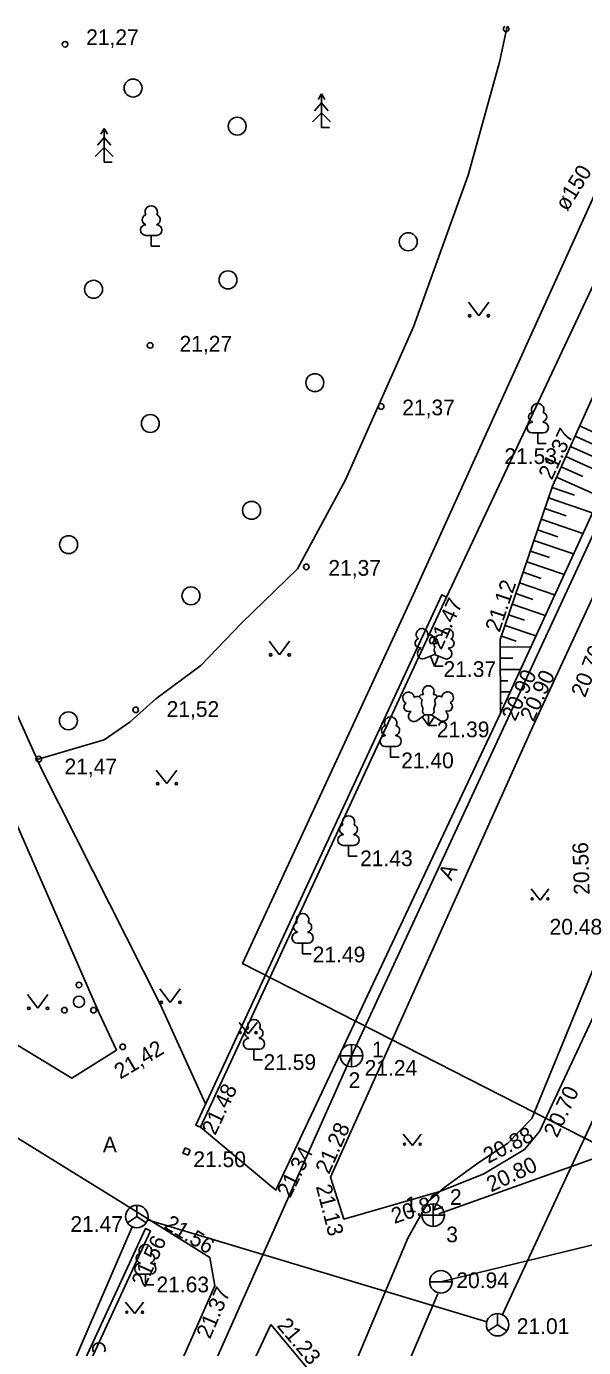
# Model space of a CAD drawing. Extents: x 714391 to 714584, y 6589993 to 6590151.
# Drawn here: x 714424.1 to 714448.9, y 6590092.2 to 6590151.1 of the extents above; entities that cross this region are included whole.
import ezdxf

# ---------------------------------------------------------------- set-up
doc = ezdxf.new("R2010")
doc.units = 0
for name, color, linetype in [('AED', 7, 'Continuous'), ('HALJASTUS', 7, 'Continuous'), ('HOONE', 7, 'Continuous'), ('KKAEV', 7, 'Continuous'), ('KORGUS', 7, 'Continuous'), ('KTRASS', 7, 'Continuous'), ('MPKAABEL', 7, 'Continuous'), ('PUU', 7, 'Continuous'), ('RELJEEF', 7, 'Continuous'), ('SIKAEV', 7, 'Continuous'), ('SITRASS', 7, 'Continuous'), ('SKKAEV', 7, 'Continuous'), ('SKTRASS', 7, 'Continuous'), ('TEE', 7, 'Continuous'), ('TORU NR', 7, 'Continuous'), ('VKAEV', 7, 'Continuous'), ('VTRASS', 7, 'Continuous')]:
    doc.layers.add(name, color=color, linetype=linetype)

msp = doc.modelspace()

# ---------------------------------------------------------------- linework, layer by layer
at = {"layer": 'AED'}
for p, q in [((714431.182, 6590101.096), (714431.081, 6590100.867)), ((714431.182, 6590101.096), (714431.411, 6590100.995)), ((714431.411, 6590100.995), (714431.31, 6590100.766)), ((714431.081, 6590100.867), (714431.31, 6590100.766))]:
    msp.add_line(p, q, dxfattribs=at)
for points in [[(714442.826, 6590125.646), (714454.774, 6590151.075)], [(714419.286, 6590087.641), (714423.948, 6590085.67), (714429.409, 6590097.501), (714429.636, 6590097.396), (714424.08, 6590085.358), (714419.194, 6590087.423)]]:
    msp.add_lwpolyline(points, dxfattribs=at)
msp.add_lwpolyline([(714431.863, 6590102.016), (714442.826, 6590125.646), (714442.618, 6590125.749), (714431.653, 6590102.114)], close=True, dxfattribs=at)
at = {"layer": 'HALJASTUS'}
for p, q in [((714443.797, 6590138.787), (714444.26, 6590138.18)), ((714444.26, 6590138.18), (714444.706, 6590138.787)), ((714434.927, 6590123.677), (714435.39, 6590123.07)), ((714435.39, 6590123.07), (714435.836, 6590123.677)), ((714429.897, 6590117.937), (714430.36, 6590117.33)), ((714430.36, 6590117.33), (714430.806, 6590117.937)), ((714446.589, 6590112.643), (714446.994, 6590112.138)), ((714446.994, 6590112.138), (714447.389, 6590112.643)), ((714430.057, 6590108.187), (714430.52, 6590107.58)), ((714430.52, 6590107.58), (714430.966, 6590108.187)), ((714424.157, 6590107.927), (714424.62, 6590107.32)), ((714424.62, 6590107.32), (714425.066, 6590107.927)), ((714433.585, 6590106.683), (714433.99, 6590106.178)), ((714433.99, 6590106.178), (714434.385, 6590106.683)), ((714440.9, 6590101.716), (714441.305, 6590101.211)), ((714441.305, 6590101.211), (714441.7, 6590101.716)), ((714428.528, 6590094.221), (714428.933, 6590093.716)), ((714428.933, 6590093.716), (714429.328, 6590094.221))]:
    msp.add_line(p, q, dxfattribs=at)
msp.add_lwpolyline([(714445.524, 6590151.075), (714445.18, 6590149.48), (714443.79, 6590144.45), (714441.36, 6590137.69), (714438.33, 6590130.87), (714436.18, 6590126.9), (714433.71, 6590124.5), (714431.88, 6590122.59), (714429.88, 6590121.11), (714428.73, 6590120.08), (714427.57, 6590119.28), (714424.59, 6590118.4)], dxfattribs=at)
for centre, radius in [((714428.86, 6590148.33), 0.4), ((714433.5, 6590146.63), 0.4), ((714441.12, 6590141.48), 0.4), ((714433.09, 6590139.78), 0.4), ((714427.1, 6590139.36), 0.4), ((714443.859, 6590138.18), 0.055), ((714444.688, 6590138.18), 0.055), ((714436.96, 6590135.2), 0.4), ((714429.63, 6590133.38), 0.4), ((714434.14, 6590129.51), 0.4), ((714425.99, 6590127.98), 0.4), ((714431.44, 6590125.7), 0.4), ((714434.989, 6590123.07), 0.055), ((714435.818, 6590123.07), 0.055), ((714425.98, 6590120.13), 0.4), ((714429.959, 6590117.33), 0.055), ((714430.788, 6590117.33), 0.055), ((714446.641, 6590112.194), 0.0428), ((714447.341, 6590112.194), 0.0452), ((714426.45, 6590108.36), 0.125), ((714426.45, 6590107.61), 0.25), ((714430.119, 6590107.58), 0.055), ((714430.948, 6590107.58), 0.055), ((714424.219, 6590107.32), 0.055), ((714425.048, 6590107.32), 0.055), ((714425.8, 6590107.235), 0.125), ((714427.1, 6590107.235), 0.125), ((714433.637, 6590106.233), 0.0428), ((714434.337, 6590106.233), 0.0452), ((714440.952, 6590101.266), 0.0428), ((714441.652, 6590101.266), 0.0452), ((714428.58, 6590093.771), 0.0428), ((714429.28, 6590093.771), 0.0452)]:
    msp.add_circle(centre, radius, dxfattribs=at)
at = {"layer": 'HOONE'}
msp.add_lwpolyline([(714462.081, 6590095.105), (714459.73, 6590096.05), (714433.74, 6590109.31), (714441.36, 6590125.77), (714449.34, 6590143.41), (714452.652, 6590151.075)], dxfattribs=at)
at = {"layer": 'KKAEV'}
for p, q in [((714438.594, 6590104.707), (714438.594, 6590105.707)), ((714438.094, 6590105.207), (714439.094, 6590105.207))]:
    msp.add_line(p, q, dxfattribs=at)
msp.add_circle((714438.594, 6590105.207), 0.5, dxfattribs=at)
at = {"layer": 'KORGUS'}
for centre in [(714425.83, 6590150.28), (714429.62, 6590136.86), (714439.91, 6590134.14), (714436.58, 6590126.99), (714428.98, 6590120.62), (714424.66, 6590118.42), (714428.4, 6590105.6)]:
    msp.add_circle(centre, 0.125, dxfattribs=at)
msp.add_arc((714445.48, 6590150.96), 0.125, 112.49, 67.51, dxfattribs=at)
at = {"layer": 'KTRASS'}
for p in [(714456.211, 6590143.264), (714431.463, 6590089.186)]:
    msp.add_line(p, (714438.594, 6590105.207), dxfattribs=at)
at = {"layer": 'MPKAABEL'}
msp.add_lwpolyline([(714394.611, 6589992.711), (714400.19, 6590004.938), (714412.114, 6590031.265), (714423.696, 6590056.183), (714434.84, 6590082.35), (714435.599, 6590083.495), (714435.59, 6590083.97), (714441.1, 6590097.08), (714442.02, 6590098.72), (714442.75, 6590099.35), (714444.22, 6590100.41), (714445.54, 6590101.3), (714446.63, 6590102.41), (714450.168, 6590111.053), (714453.153, 6590116.846), (714463.66, 6590139.57), (714466.53, 6590147), (714468.444, 6590151.075)], dxfattribs=at)
at = {"layer": 'PUU'}
for p, q in [((714437.25, 6590148.07), (714437.1, 6590147.82)), ((714437.4, 6590147.82), (714437.25, 6590148.07)), ((714437.25, 6590148.07), (714437.25, 6590146.57)), ((714437.25, 6590147.67), (714436.95, 6590147.32)), ((714437.55, 6590147.32), (714437.25, 6590147.67)), ((714437.25, 6590147.22), (714436.85, 6590146.82)), ((714437.65, 6590146.82), (714437.25, 6590147.22)), ((714427.57, 6590146.53), (714427.42, 6590146.28)), ((714427.72, 6590146.28), (714427.57, 6590146.53)), ((714427.57, 6590146.53), (714427.57, 6590145.03)), ((714437.61, 6590146.57), (714437.25, 6590146.57)), ((714427.57, 6590146.13), (714427.27, 6590145.78)), ((714427.87, 6590145.78), (714427.57, 6590146.13)), ((714427.57, 6590145.68), (714427.17, 6590145.28)), ((714427.97, 6590145.28), (714427.57, 6590145.68)), ((714427.93, 6590145.03), (714427.57, 6590145.03)), ((714429.91, 6590141.765), (714429.43, 6590141.765)), ((714429.67, 6590141.29), (714429.67, 6590141.765)), ((714430.05, 6590141.29), (714429.67, 6590141.29)), ((714446.646, 6590133.462), (714446.646, 6590133.432)), ((714447.126, 6590133.462), (714447.126, 6590133.432)), ((714447.126, 6590132.957), (714446.646, 6590132.957)), ((714446.886, 6590132.482), (714446.886, 6590132.957)), ((714447.266, 6590132.482), (714446.886, 6590132.482)), ((714441.674, 6590123.351), (714441.659, 6590123.391)), ((714442.204, 6590123.561), (714442.189, 6590123.596)), ((714442.389, 6590123.556), (714442.404, 6590123.596)), ((714442.914, 6590123.341), (714442.929, 6590123.381)), ((714441.849, 6590122.906), (714442.294, 6590123.081)), ((714442.289, 6590122.571), (714442.114, 6590123.011)), ((714442.289, 6590122.571), (714442.469, 6590123.011)), ((714442.294, 6590123.081), (714442.734, 6590122.901)), ((714442.669, 6590122.571), (714442.289, 6590122.571)), ((714441.23, 6590120.52), (714441.205, 6590120.555)), ((714442.79, 6590120.535), (714442.81, 6590120.57)), ((714441.505, 6590120.135), (714441.865, 6590120.39)), ((714442.015, 6590119.915), (714441.74, 6590120.3)), ((714441.865, 6590120.39), (714442.16, 6590120.39)), ((714442.015, 6590119.915), (714442.015, 6590120.39)), ((714442.015, 6590119.915), (714442.285, 6590120.305)), ((714442.395, 6590119.915), (714442.015, 6590119.915)), ((714442.16, 6590120.39), (714442.52, 6590120.145)), ((714440.094, 6590119.492), (714440.094, 6590119.462)), ((714440.574, 6590119.492), (714440.574, 6590119.462)), ((714440.574, 6590118.987), (714440.094, 6590118.987)), ((714440.334, 6590118.512), (714440.334, 6590118.987)), ((714440.714, 6590118.512), (714440.334, 6590118.512)), ((714438.218, 6590115.082), (714438.218, 6590115.052)), ((714438.698, 6590114.577), (714438.218, 6590114.577)), ((714438.458, 6590114.102), (714438.458, 6590114.577)), ((714438.698, 6590115.082), (714438.698, 6590115.052)), ((714438.838, 6590114.102), (714438.458, 6590114.102)), ((714436.175, 6590110.727), (714436.175, 6590110.697)), ((714436.655, 6590110.727), (714436.655, 6590110.697)), ((714436.655, 6590110.222), (714436.175, 6590110.222)), ((714436.415, 6590109.747), (714436.415, 6590110.222)), ((714436.795, 6590109.747), (714436.415, 6590109.747)), ((714434.007, 6590106.002), (714434.007, 6590105.972)), ((714434.487, 6590106.002), (714434.487, 6590105.972)), ((714434.487, 6590105.497), (714434.007, 6590105.497)), ((714434.247, 6590105.022), (714434.247, 6590105.497)), ((714434.627, 6590105.022), (714434.247, 6590105.022)), ((714429.168, 6590095.976), (714429.168, 6590095.946)), ((714429.648, 6590095.976), (714429.648, 6590095.946)), ((714429.648, 6590095.471), (714429.168, 6590095.471)), ((714429.408, 6590094.996), (714429.408, 6590095.471)), ((714429.788, 6590094.996), (714429.408, 6590094.996))]:
    msp.add_line(p, q, dxfattribs=at)
for points in [[(714442.294, 6590123.576), (714442.274, 6590123.501), (714442.274, 6590123.481), (714442.284, 6590123.451), (714442.304, 6590123.416), (714442.309, 6590123.396), (714442.294, 6590123.361), (714442.269, 6590123.311), (714442.264, 6590123.286), (714442.269, 6590123.271), (714442.279, 6590123.241), (714442.314, 6590123.181), (714442.319, 6590123.161), (714442.314, 6590123.141), (714442.299, 6590123.106), (714442.294, 6590123.081)], [(714441.6, 6590121.2), (714441.705, 6590121.1), (714441.72, 6590121.07), (714441.72, 6590121.015), (714441.705, 6590120.925), (714441.705, 6590120.88), (714441.725, 6590120.8), (714441.765, 6590120.71), (714441.775, 6590120.665), (714441.77, 6590120.62), (714441.755, 6590120.555), (714441.755, 6590120.525), (714441.775, 6590120.485), (714441.8, 6590120.455), (714441.865, 6590120.39)], [(714442.42, 6590121.215), (714442.325, 6590121.1), (714442.31, 6590121.07), (714442.31, 6590121.015), (714442.325, 6590120.925), (714442.33, 6590120.88), (714442.31, 6590120.8), (714442.27, 6590120.71), (714442.26, 6590120.665), (714442.265, 6590120.62), (714442.28, 6590120.555), (714442.28, 6590120.525), (714442.26, 6590120.485), (714442.235, 6590120.455), (714442.165, 6590120.39)]]:
    msp.add_lwpolyline(points, dxfattribs=at)
for centre, radius, start, end in [((714429.67, 6590142.81), 0.277, 332.5799, 207.4201), ((714429.433, 6590142.002), 0.238, 90.0016, 269.3953), ((714429.5, 6590142.463), 0.233, 109.02174, 253.14154), ((714429.84, 6590142.463), 0.233, 286.85082, 70.98591), ((714429.907, 6590142.002), 0.238, 270.6047, 89.9984), ((714446.886, 6590134.002), 0.277, 332.5799, 207.4201), ((714446.649, 6590133.195), 0.237, 90.00001, 270), ((714446.696, 6590133.67), 0.212, 105.2441, 257.07903), ((714447.076, 6590133.67), 0.212, 282.92097, 74.7559), ((714447.124, 6590133.195), 0.237, 270, 89.99999), ((714441.732, 6590123.985), 0.256, 111.50269, 232.51731), ((714441.732, 6590123.985), 0.256, 350.48556, 111.50017), ((714442.075, 6590123.763), 0.202, 305.13446, 116.70496), ((714442.522, 6590123.759), 0.202, 62.41201, 233.98252), ((714442.868, 6590123.976), 0.256, 67.6168, 188.63142), ((714442.868, 6590123.976), 0.256, 306.59966, 67.61428), ((714441.633, 6590123.589), 0.202, 106.29791, 277.86841), ((714441.763, 6590123.129), 0.237, 111.50143, 291.50036), ((714442.293, 6590123.338), 0.237, 66.76552, 111.50149), ((714442.824, 6590123.121), 0.237, 247.61661, 67.61554), ((714442.961, 6590123.579), 0.202, 261.24856, 72.81907), ((714442.015, 6590121.435), 0.256, 90.00126, 211.01588), ((714442.015, 6590121.435), 0.256, 328.98412, 89.99874), ((714441.132, 6590121.152), 0.256, 125.53894, 246.55356), ((714441.132, 6590121.152), 0.256, 4.5218, 125.53642), ((714441.518, 6590121.019), 0.202, 65.23821, 130.74121), ((714441.777, 6590121.103), 0.202, 84.79647, 150.29947), ((714442.252, 6590121.103), 0.202, 34.38566, 95.20353), ((714442.491, 6590121.028), 0.202, 50.31726, 111.13512), ((714442.875, 6590121.168), 0.256, 55.52204, 176.53666), ((714442.875, 6590121.168), 0.256, 294.50491, 55.51952), ((714441.132, 6590120.743), 0.202, 120.33415, 291.90466), ((714441.369, 6590120.329), 0.237, 125.53768, 305.53661), ((714442.653, 6590120.341), 0.237, 235.52186, 55.52078), ((714442.883, 6590120.759), 0.202, 249.15381, 60.72431), ((714440.144, 6590119.7), 0.212, 105.2441, 257.07903), ((714440.334, 6590120.032), 0.277, 332.5799, 207.4201), ((714440.524, 6590119.7), 0.212, 282.92097, 74.7559), ((714440.096, 6590119.225), 0.237, 90.00001, 270), ((714440.571, 6590119.225), 0.237, 270, 89.99999), ((714438.458, 6590115.622), 0.277, 332.5799, 207.4201), ((714438.268, 6590115.29), 0.212, 105.2441, 257.07903), ((714438.648, 6590115.29), 0.212, 282.92097, 74.7559), ((714438.22, 6590114.815), 0.237, 90.00001, 270), ((714438.695, 6590114.815), 0.237, 270, 89.99999), ((714436.225, 6590110.935), 0.212, 105.2441, 257.07903), ((714436.415, 6590111.267), 0.277, 332.5799, 207.4201), ((714436.605, 6590110.935), 0.212, 282.92097, 74.7559), ((714436.177, 6590110.46), 0.237, 90.00001, 270), ((714436.652, 6590110.46), 0.237, 270, 89.99999), ((714434.057, 6590106.21), 0.212, 105.2441, 257.07903), ((714434.247, 6590106.542), 0.277, 332.5799, 207.4201), ((714434.437, 6590106.21), 0.212, 282.92097, 74.7559), ((714434.009, 6590105.735), 0.237, 90.00001, 270), ((714434.484, 6590105.735), 0.237, 270, 89.99999), ((714429.218, 6590096.184), 0.212, 105.2441, 257.07903), ((714429.408, 6590096.516), 0.277, 332.5799, 207.4201), ((714429.598, 6590096.184), 0.212, 282.92097, 74.7559), ((714429.171, 6590095.709), 0.237, 90.00001, 270), ((714429.645, 6590095.709), 0.237, 270, 89.99999), ((714427.337, 6590092.14), 0.277, 332.5799, 207.4201)]:
    msp.add_arc(centre, radius, start, end, dxfattribs=at)
at = {"layer": 'RELJEEF'}
for p, q in [((714450.49, 6590131.939), (714448.549, 6590132.814)), ((714449.727, 6590132.832), (714448.755, 6590133.27)), ((714449.313, 6590131.922), (714448.344, 6590132.358)), ((714450.073, 6590131.031), (714448.138, 6590131.903)), ((714449.655, 6590130.122), (714447.727, 6590130.991)), ((714448.898, 6590131.012), (714447.933, 6590131.447)), ((714448.529, 6590130.192), (714447.528, 6590130.533)), ((714449.321, 6590129.394), (714447.366, 6590130.06)), ((714448.158, 6590129.262), (714447.205, 6590129.586)), ((714447.787, 6590128.332), (714446.882, 6590128.64)), ((714448.901, 6590128.48), (714447.044, 6590129.113)), ((714448.481, 6590127.567), (714446.721, 6590128.167)), ((714447.416, 6590127.402), (714446.56, 6590127.693)), ((714448.062, 6590126.653), (714446.399, 6590127.22)), ((714447.045, 6590126.472), (714446.237, 6590126.747)), ((714446.674, 6590125.542), (714445.915, 6590125.8)), ((714447.642, 6590125.74), (714446.076, 6590126.273)), ((714447.223, 6590124.826), (714445.753, 6590125.327)), ((714446.302, 6590124.612), (714445.592, 6590124.854)), ((714446.803, 6590123.913), (714445.431, 6590124.38)), ((714446.576, 6590123.42), (714445.217, 6590123.416)), ((714445.931, 6590123.682), (714445.27, 6590123.907)), ((714445.782, 6590122.917), (714445.218, 6590122.916)), ((714446.116, 6590122.418), (714445.22, 6590122.416)), ((714445.554, 6590121.917), (714445.221, 6590121.916)), ((714445.656, 6590121.417), (714445.222, 6590121.416)), ((714445.325, 6590120.916), (714445.224, 6590120.916))]:
    msp.add_line(p, q, dxfattribs=at)
msp.add_lwpolyline([(714456.989, 6590151.075), (714452.93, 6590142.535), (714447.548, 6590130.593), (714445.216, 6590123.75), (714445.225, 6590120.478)], dxfattribs=at)
at = {"layer": 'SIKAEV'}
for p, q in [((714429.027, 6590098.034), (714428.612, 6590097.759)), ((714429.027, 6590098.534), (714429.027, 6590098.034)), ((714429.027, 6590098.034), (714429.442, 6590097.759)), ((714445.101, 6590093.718), (714445.101, 6590093.218)), ((714445.101, 6590093.218), (714444.686, 6590092.943)), ((714445.101, 6590093.218), (714445.516, 6590092.943))]:
    msp.add_line(p, q, dxfattribs=at)
for centre in [(714429.027, 6590098.034), (714445.101, 6590093.218)]:
    msp.add_circle(centre, 0.5, dxfattribs=at)
at = {"layer": 'SITRASS'}
for p, q in [((714445.318, 6590093.669), (714471.983, 6590151.075)), ((714428.828, 6590097.575), (714403.181, 6590038.435)), ((714444.617, 6590093.345), (714429.506, 6590097.89))]:
    msp.add_line(p, q, dxfattribs=at)
at = {"layer": 'SKKAEV'}
for p, q in [((714441.73, 6590098.1), (714442.73, 6590098.1)), ((714442.23, 6590097.6), (714442.23, 6590098.6))]:
    msp.add_line(p, q, dxfattribs=at)
msp.add_circle((714442.23, 6590098.1), 0.5, dxfattribs=at)
at = {"layer": 'SKTRASS'}
msp.add_line((714442.481, 6590098.162), (714456.8, 6590103.262), dxfattribs=at)
at = {"layer": 'TEE'}
for points in [[(714390.649, 6590129.095), (714393.48, 6590126.4), (714398.09, 6590122.89), (714405.06, 6590117.58), (714409.44, 6590114.75), (714418.17, 6590109.03), (714426.14, 6590104.21), (714428.12, 6590105.45), (714427.35, 6590107.1), (714423.67, 6590115.54), (714421.09, 6590120.78), (714420.48, 6590122.28), (714417.81, 6590128.52), (714415.91, 6590134.31), (714414.98, 6590136.15), (714411.88, 6590140.9), (714408.53, 6590145.77), (714404.9, 6590150.82), (714404.697, 6590151.075)], [(714408.052, 6590151.075), (714408.37, 6590150.6), (714411.69, 6590145.93), (714414.39, 6590142.16), (714415.93, 6590139.44), (714418.07, 6590135.51), (714418.66, 6590133.97), (714419.22, 6590131.63), (714420.13, 6590128.75), (714420.96, 6590126.45), (714424.8, 6590117.94), (714430.08, 6590107.48), (714432.094, 6590103.064)], [(714431.863, 6590102.016), (714435.225, 6590099.219), (714445.225, 6590120.478), (714454.134, 6590139.871), (714458.283, 6590149.057), (714459.223, 6590151.075)], [(714461.172, 6590151.075), (714459.316, 6590147.116), (714455.509, 6590138.934), (714446.669, 6590119.883), (714437.663, 6590099.797), (714438.254, 6590097.927), (714442.53, 6590099.149)], [(714390.65, 6590124.59), (714396, 6590120.47), (714402.53, 6590115.27), (714412.65, 6590108.38), (714428.405, 6590098.635), (714430.062, 6590097.596), (714432.277, 6590096.218), (714432.498, 6590094.946), (714428.283, 6590085.404), (714423.452, 6590074.702), (714420.733, 6590068.851), (714418.831, 6590064.457), (714408.849, 6590042.202), (714401.401, 6590025.886)], [(714442.53, 6590099.149), (714444.488, 6590099.946), (714446.305, 6590101.019), (714446.966, 6590101.823), (714450.542, 6590109.47)], [(714435, 6590093.228), (714431.011, 6590084.697), (714429.842, 6590082.14)], [(714435, 6590093.228), (714437.473, 6590090.263), (714438.044, 6590089.173), (714438.287, 6590088.162), (714438.124, 6590086.085)]]:
    msp.add_lwpolyline(points, dxfattribs=at)
at = {"layer": 'VKAEV'}
msp.add_line((714442.077, 6590095.127), (714443.077, 6590095.127), dxfattribs=at)
msp.add_circle((714442.577, 6590095.127), 0.5, dxfattribs=at)
at = {"layer": 'VTRASS'}
for p, q in [((714442.577, 6590095.127), (714487.91, 6590106.151)), ((714442.442, 6590094.595), (714426.529, 6590057.51))]:
    msp.add_line(p, q, dxfattribs=at)

# ---------------------------------------------------------------- texts
at = {"layer": 'KORGUS'}
for s, p in [('21,27', (714426.771, 6590150.245)), ('21,27', (714430.931, 6590136.585)), ('21,37', (714440.851, 6590133.745)), ('21.53', (714445.403, 6590131.575)), ('21,37', (714437.561, 6590126.595)), ('21.37', (714442.692, 6590122.087)), ('21,52', (714430.356, 6590120.305)), ('21.39', (714442.395, 6590119.397)), ('21.40', (714440.806, 6590118.016)), ('21,47', (714425.806, 6590117.745)), ('21.43', (714438.976, 6590113.652)), ('20.48', (714447.415, 6590110.603)), ('21.49', (714436.864, 6590109.366)), ('21.59', (714434.673, 6590104.572)), ('21.24', (714439.178, 6590104.312)), ('21.50', (714431.546, 6590100.241)), ('21.47', (714426.069, 6590097.356)), ('21.63', (714429.903, 6590094.661)), ('20.94', (714443.262, 6590094.849)), ('21.01', (714445.956, 6590092.804))]:
    msp.add_text(s, height=0.7, dxfattribs=at).set_placement(p)
for s, rotation, p in [('21.37', 64.6684, (714447.515, 6590130.827)), ('21.12', 71.33309, (714445.188, 6590124.042)), ('21.47', 65.40021, (714442.593, 6590123.258)), ('20.76', 68.51456, (714448.996, 6590121.13)), ('20.90', 65.44955, (714445.887, 6590120.076)), ('20.90', 65.17946, (714446.696, 6590120.055)), ('20.56', 91.78991, (714449.201, 6590112.387)), ('21,42', 30.84925, (714428.288, 6590104.135)), ('21.48', 64.65382, (714432.519, 6590101.625)), ('20.70', 64.96247, (714447.753, 6590101.514)), ('21.28', 65.94747, (714437.589, 6590099.887)), ('20.88', 27.06294, (714444.683, 6590100.386)), ('21.34', 63.43495, (714435.861, 6590098.833)), ('20.80', 25.12997, (714444.812, 6590099.11)), ('21.13', 284.5404, (714436.998, 6590099.378)), ('20.82', 18.30662, (714440.497, 6590097.707)), ('21.56', 328.86969, (714430.198, 6590097.551)), ('21.56', 65.47732, (714429.392, 6590094.85)), ('21.37', 66.50143, (714432.286, 6590092.545)), ('21.23', 310.0862, (714435.236, 6590093.161))]:
    msp.add_text(s, height=0.7, rotation=rotation, dxfattribs=at).set_placement(p)
at = {"layer": 'TEE'}
msp.add_text('A', height=0.7, rotation=62.8402, dxfattribs=at).set_placement((714443.041, 6590112.969))
msp.add_text('A', height=0.7, dxfattribs=at).set_placement((714427.514, 6590100.9))
at = {"layer": 'TORU NR'}
msp.add_text('ø150', height=0.7, rotation=58.16106, dxfattribs=at).set_placement((714448.203, 6590142.804))
for s, p in [('1', (714439.502, 6590105.135)), ('2', (714438.462, 6590103.766)), ('2', (714442.978, 6590098.558)), ('1', (714440.981, 6590098.228)), ('3', (714442.813, 6590096.891))]:
    msp.add_text(s, height=0.7, dxfattribs=at).set_placement(p)

doc.saveas('drawing.dxf')
